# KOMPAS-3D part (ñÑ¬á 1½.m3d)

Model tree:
1. Эскиз:1
2. Операция выдавливания:1
     Расстояние 1 = 0.6
3. Эскиз:2
4. Вырезать элемент выдавливания:1
     Толщина стенки 1 = 3; Толщина стенки 2 = 3; Расстояние 1 = 10
5. Эскиз:3
6. Вырезать элемент выдавливания:2
     Толщина стенки 1 = 3; Толщина стенки 2 = 3; Расстояние 1 = 10
7. Эскиз:4
8. Вырезать элемент выдавливания:3
     Толщина стенки 1 = 3; Толщина стенки 2 = 3; Расстояние 1 = 10
9. Эскиз:5
10. Вырезать элемент выдавливания:4
     Толщина стенки 1 = 3; Толщина стенки 2 = 3; Расстояние 1 = 10
